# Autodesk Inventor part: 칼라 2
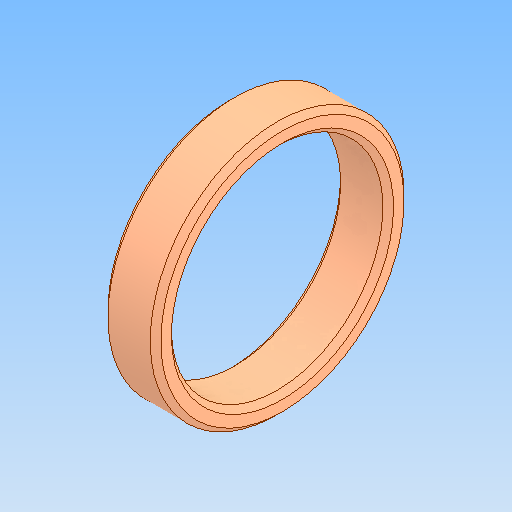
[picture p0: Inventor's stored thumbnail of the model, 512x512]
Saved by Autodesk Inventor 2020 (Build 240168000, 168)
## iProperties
Created: 2025-11
Part Number: 칼라 2
Material: 강철, 연강
Document SubType Name: Modeling
Designer: PC2-06
Density: 7.85 g/cm^3
Appearance: 기본값
Author: jhkim
Sending System: Autodesk Inventor 2026
Preprocessor: ST-DEVELOPER v20.1
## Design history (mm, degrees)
feature "솔리드1"
node "솔리드2"
